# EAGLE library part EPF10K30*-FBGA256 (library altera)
EPF10K30 FLEX 10K family
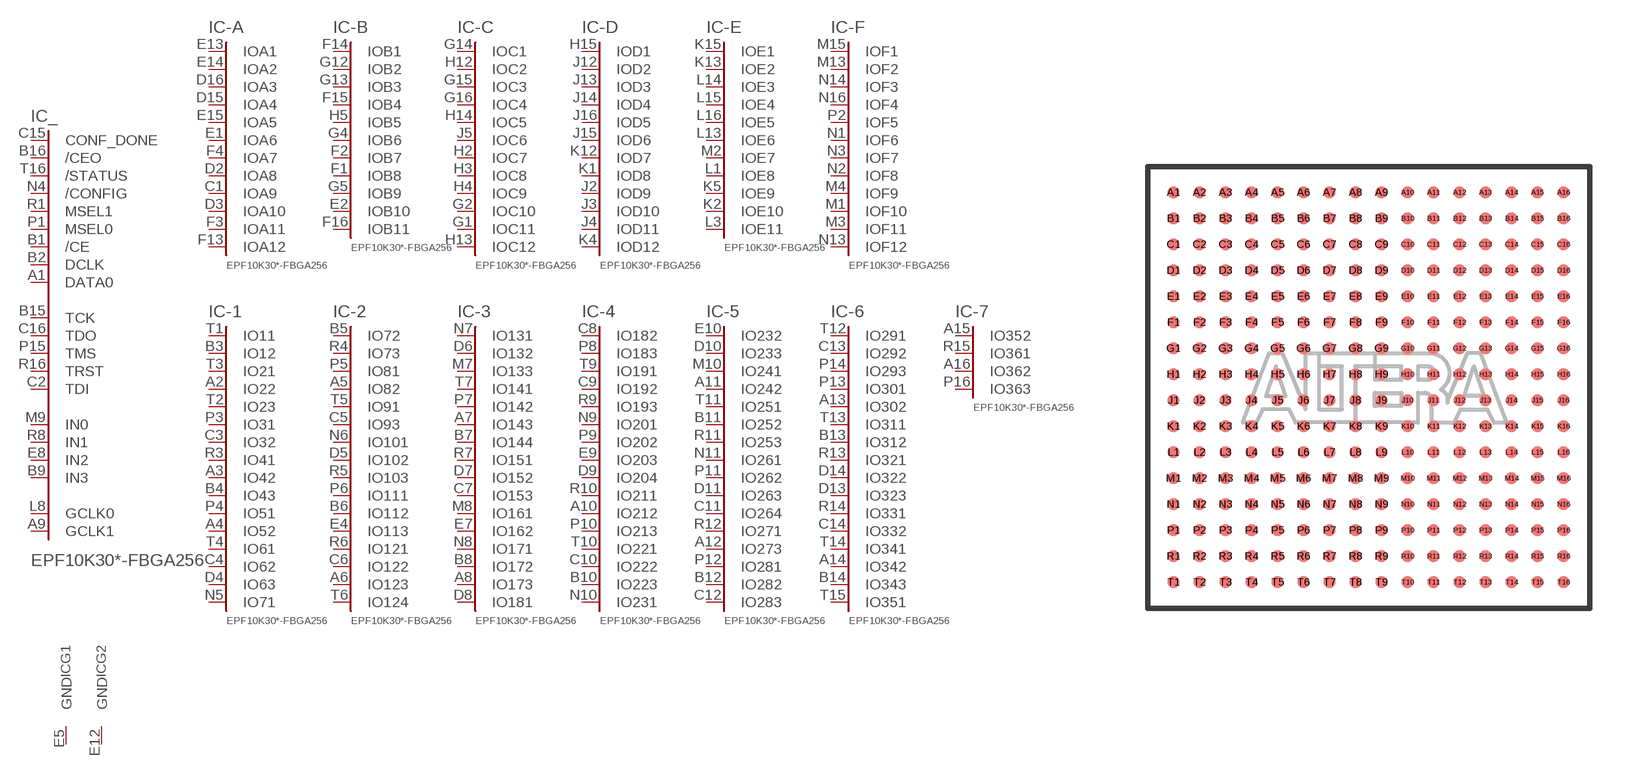
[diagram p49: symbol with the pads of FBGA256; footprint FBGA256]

Designator prefix IC; gates _=100R240C -A=A12 -B=B11 -C=C12 -D=D12 -E=E11 -F=F12 -1=71-K30EF -2=124-K30E -3=181-K30E -4=231-K30E -5=281-K30E -6=351-K30E -7=363-K30E G1=GND G2=GND G3=GND G4=GND G5=GND G6=GND G7=GND G8=GND G9=GND G10=GND G11=GND G12=GND G13=GND G14=GND G15=GND G16=GND G17=GND G18=GND NC1=NC NC2=NC NC3=NC NC4=NC NC5=NC NC6=NC NC7=NC NC8=NC NC9=NC NC10=NC NC11=NC NC12=NC NC13=NC NC14=NC NC15=NC V1=VCCINT V2=VCCINT V3=VCCINT V4=VCCINT V5=VCCINT V6=VCCINT V7=VCCINT V8=VCCINT V9=VCCINT V10=VCCINT V11=VCCINT V12=VCCINT V13=VCCINT V14=VCCINT V15=VCCINT V16=VCCINT V17=VCCINT V18=VCCINT VO1=VCCIO VO2=VCCIO VO3=VCCIO VO4=VCCIO VO5=VCCIO VO6=VCCIO VO7=VCCIO VO8=VCCIO VO9=VCCIO VO10=VCCIO VO11=VCCIO VO12=VCCIO VO13=VCCIO VO14=VCCIO VO15=VCCIO

## EPF10K30-FBGA256 (MPN: EPF10K30EFC256-3N; OC_FARNELL: 1549394; OC_NEWARK: 51R8977), EPF10K30A-FBGA256 (MPN: EPF10K30AQC240-3N; OC_FARNELL: 1549384; OC_NEWARK: 51R8956)  [FBGA256]
A1  _:DATA0  in
A2  -1:IO22
A3  -1:IO42
A4  -1:IO52
A5  -2:IO82
A6  -2:IO123
A7  -3:IO143
A8  -3:IO173
A9  _:GCLK1  in
A10  -4:IO212
A11  -5:IO242
A12  -5:IO273
A13  -6:IO302
A14  -6:IO342
A15  -7:IO352
A16  -7:IO362
B1  _:/CE  in
B2  _:DCLK  in
B3  -1:IO12
B4  -1:IO43
B5  -2:IO72
B6  -2:IO112
B7  -3:IO144
B8  -3:IO172
B9  _:IN3  in
B10  -4:IO223
B11  -5:IO252
B12  -5:IO282
B13  -6:IO312
B14  -6:IO343
B15  _:TCK
B16  _:/CEO  in
C1  -A:IOA9
C2  _:TDI
C3  -1:IO32
C4  -1:IO62
C5  -2:IO93
C6  -2:IO122
C7  -3:IO153
C8  -4:IO182
C9  -4:IO192
C10  -4:IO222
C11  -5:IO264
C12  -5:IO283
C13  -6:IO292
C14  -6:IO332
C15  _:CONF_DONE  in
C16  _:TDO
D1  NC1:NC  nc
D2  -A:IOA8
D3  -A:IOA10
D4  -1:IO63
D5  -2:IO102
D6  -3:IO132
D7  -3:IO152
D8  -3:IO181
D9  -4:IO204
D10  -5:IO233
D11  -5:IO263
D12  VO1:VCCIO  pwr
D13  -6:IO323
D14  -6:IO322
D15  -A:IOA4
D16  -A:IOA3
E1  -A:IOA6
E2  -B:IOB10
E3  NC2:NC  nc
E4  -2:IO113
E5  G1:GND  pwr
E6  VO2:VCCIO  pwr
E7  -3:IO162
E8  _:IN2  in
E9  -4:IO203
E10  -5:IO232
E11  V1:VCC  pwr
E12  G2:GND  pwr
E13  -A:IOA1
E14  -A:IOA2
E15  -A:IOA5
E16  NC3:NC  nc
F1  -B:IOB8
F2  -B:IOB7
F3  -A:IOA11
F4  -A:IOA7
F5  V2:VCC  pwr
F6  G3:GND  pwr
F7  V3:VCC  pwr
F8  VO3:VCCIO  pwr
F9  V4:VCC  pwr
F10  VO4:VCCIO  pwr
F11  G4:GND  pwr
F12  V5:VCC  pwr
F13  -A:IOA12
F14  -B:IOB1
F15  -B:IOB4
F16  -B:IOB11
G1  -C:IOC11
G2  -C:IOC10
G3  NC4:NC  nc
G4  -B:IOB6
G5  -B:IOB9
G6  VO5:VCCIO  pwr
G7  G5:GND  pwr
G8  VO6:VCCIO  pwr
G9  G6:GND  pwr
G10  G7:GND  pwr
G11  VO7:VCCIO  pwr
G12  -B:IOB2
G13  -B:IOB3
G14  -C:IOC1
G15  -C:IOC3
G16  -C:IOC4
H1  NC5:NC  nc
H2  -C:IOC7
H3  -C:IOC8
H4  -C:IOC9
H5  -B:IOB5
H6  V6:VCC  pwr
H7  V7:VCC  pwr
H8  G8:GND  pwr
H9  G9:GND  pwr
H10  V8:VCC  pwr
H11  VO8:VCCIO  pwr
H12  -C:IOC2
H13  -C:IOC12
H14  -C:IOC5
H15  -D:IOD1
H16  NC6:NC  nc
J1  NC7:NC  nc
J2  -D:IOD9
J3  -D:IOD10
J4  -D:IOD11
J5  -C:IOC6
J6  VO9:VCCIO  pwr
J7  V9:VCC  pwr
J8  G10:GND  pwr
J9  G11:GND  pwr
J10  V10:VCC  pwr
J11  V11:VCC  pwr
J12  -D:IOD2
J13  -D:IOD3
J14  -D:IOD4
J15  -D:IOD6
J16  -D:IOD5
K1  -D:IOD8
K2  -E:IOE10
K3  NC8:NC  nc
K4  -D:IOD12
K5  -E:IOE9
K6  VO10:VCCIO  pwr
K7  G12:GND  pwr
K8  VO11:VCCIO  pwr
K9  V12:VCC  pwr
K10  G13:GND  pwr
K11  VO12:VCCIO  pwr
K12  -D:IOD7
K13  -E:IOE2
K14  NC9:NC  nc
K15  -E:IOE1
K16  NC10:NC  nc
L1  -E:IOE8
L2  NC11:NC  nc
L3  -E:IOE11
L4  NC12:NC  nc
L5  V13:VCC  pwr
L6  G14:GND  pwr
L7  V14:VCC  pwr
L8  _:GCLK0  in
L9  V15:VCC  pwr
L10  VO13:VCCIO  pwr
L11  G15:GND  pwr
L12  V16:VCC  pwr
L13  -E:IOE6
L14  -E:IOE3
L15  -E:IOE4
L16  -E:IOE5
M1  -F:IOF10
M2  -E:IOE7
M3  -F:IOF11
M4  -F:IOF9
M5  G16:GND  pwr
M6  VO14:VCCIO  pwr
M7  -3:IO133
M8  -3:IO161
M9  _:IN0  in
M10  -5:IO241
M11  V17:VCC  pwr
M12  G17:GND  pwr
M13  -F:IOF2
M14  NC13:NC  nc
M15  -F:IOF1
M16  NC14:NC  nc
N1  -F:IOF6
N2  -F:IOF8
N3  -F:IOF7
N4  _:/CONFIG  in
N5  -1:IO71
N6  -2:IO101
N7  -3:IO131
N8  -3:IO171
N9  -4:IO201
N10  -4:IO231
N11  -5:IO261
N12  VO15:VCCIO  pwr
N13  -F:IOF12
N14  -F:IOF3
N15  NC15:NC  nc
N16  -F:IOF4
P1  _:MSEL0  in
P2  -F:IOF5
P3  -1:IO31
P4  -1:IO51
P5  -2:IO81
P6  -2:IO111
P7  -3:IO142
P8  -4:IO183
P9  -4:IO202
P10  -4:IO213
P11  -5:IO262
P12  -5:IO281
P13  -6:IO301
P14  -6:IO293
P15  _:TMS
P16  -7:IO363
R1  _:MSEL1  in
R2  V18:VCC  pwr
R3  -1:IO41
R4  -2:IO73
R5  -2:IO103
R6  -2:IO121
R7  -3:IO151
R8  _:IN1  in
R9  -4:IO193
R10  -4:IO211
R11  -5:IO253
R12  -5:IO271
R13  -6:IO321
R14  -6:IO331
R15  -7:IO361
R16  _:TRST
T1  -1:IO11
T2  -1:IO23
T3  -1:IO21
T4  -1:IO61
T5  -2:IO91
T6  -2:IO124
T7  -3:IO141
T8  G18:GND  pwr
T9  -4:IO191
T10  -4:IO221
T11  -5:IO251
T12  -6:IO291
T13  -6:IO311
T14  -6:IO341
T15  -6:IO351
T16  _:/STATUS  in

## Footprint FBGA256 (pad centres in mm)
Fine Ball Grid Array
smd 0.45 x 0.45: A1 -7.5,7.5; A2 -6.5,7.5; A3 -5.5,7.5; A4 -4.5,7.5; A5 -3.5,7.5; A6 -2.5,7.5; A7 -1.5,7.5; A8 -0.5,7.5; A9 0.5,7.5; A10 1.5,7.5; A11 2.5,7.5; A12 3.5,7.5; A13 4.5,7.5; A14 5.5,7.5; A15 6.5,7.5; A16 7.5,7.5; B1 -7.5,6.5; B2 -6.5,6.5; B3 -5.5,6.5; B4 -4.5,6.5; B5 -3.5,6.5; B6 -2.5,6.5; B7 -1.5,6.5; B8 -0.5,6.5; B9 0.5,6.5; B10 1.5,6.5; B11 2.5,6.5; B12 3.5,6.5; B13 4.5,6.5; B14 5.5,6.5; B15 6.5,6.5; B16 7.5,6.5; C1 -7.5,5.5; C2 -6.5,5.5; C3 -5.5,5.5; C4 -4.5,5.5; C5 -3.5,5.5; C6 -2.5,5.5; C7 -1.5,5.5; C8 -0.5,5.5; C9 0.5,5.5; C10 1.5,5.5; C11 2.5,5.5; C12 3.5,5.5; C13 4.5,5.5; C14 5.5,5.5; C15 6.5,5.5; C16 7.5,5.5; D1 -7.5,4.5; D2 -6.5,4.5; D3 -5.5,4.5; D4 -4.5,4.5; D5 -3.5,4.5; D6 -2.5,4.5; D7 -1.5,4.5; D8 -0.5,4.5; D9 0.5,4.5; D10 1.5,4.5; D11 2.5,4.5; D12 3.5,4.5; D13 4.5,4.5; D14 5.5,4.5; D15 6.5,4.5; D16 7.5,4.5; E1 -7.5,3.5; E2 -6.5,3.5; E3 -5.5,3.5; E4 -4.5,3.5; E5 -3.5,3.5; E6 -2.5,3.5; E7 -1.5,3.5; E8 -0.5,3.5; E9 0.5,3.5; E10 1.5,3.5; E11 2.5,3.5; E12 3.5,3.5; E13 4.5,3.5; E14 5.5,3.5; E15 6.5,3.5; E16 7.5,3.5; F1 -7.5,2.5; F2 -6.5,2.5; F3 -5.5,2.5; F4 -4.5,2.5; F5 -3.5,2.5; F6 -2.5,2.5; F7 -1.5,2.5; F8 -0.5,2.5; F9 0.5,2.5; F10 1.5,2.5; F11 2.5,2.5; F12 3.5,2.5; F13 4.5,2.5; F14 5.5,2.5; F15 6.5,2.5; F16 7.5,2.5; G1 -7.5,1.5; G2 -6.5,1.5; G3 -5.5,1.5; G4 -4.5,1.5; G5 -3.5,1.5; G6 -2.5,1.5; G7 -1.5,1.5; G8 -0.5,1.5; G9 0.5,1.5; G10 1.5,1.5; G11 2.5,1.5; G12 3.5,1.5; G13 4.5,1.5; G14 5.5,1.5; G15 6.5,1.5; G16 7.5,1.5; H1 -7.5,0.5; H2 -6.5,0.5; H3 -5.5,0.5; H4 -4.5,0.5; H5 -3.5,0.5; H6 -2.5,0.5; H7 -1.5,0.5; H8 -0.5,0.5; H9 0.5,0.5; H10 1.5,0.5; H11 2.5,0.5; H12 3.5,0.5; H13 4.5,0.5; H14 5.5,0.5; H15 6.5,0.5; H16 7.5,0.5; J1 -7.5,-0.5; J2 -6.5,-0.5; J3 -5.5,-0.5; J4 -4.5,-0.5; J5 -3.5,-0.5; J6 -2.5,-0.5; J7 -1.5,-0.5; J8 -0.5,-0.5; J9 0.5,-0.5; J10 1.5,-0.5; J11 2.5,-0.5; J12 3.5,-0.5; J13 4.5,-0.5; J14 5.5,-0.5; J15 6.5,-0.5; J16 7.5,-0.5; K1 -7.5,-1.5; K2 -6.5,-1.5; K3 -5.5,-1.5; K4 -4.5,-1.5; K5 -3.5,-1.5; K6 -2.5,-1.5; K7 -1.5,-1.5; K8 -0.5,-1.5; K9 0.5,-1.5; K10 1.5,-1.5; K11 2.5,-1.5; K12 3.5,-1.5; K13 4.5,-1.5; K14 5.5,-1.5; K15 6.5,-1.5; K16 7.5,-1.5; L1 -7.5,-2.5; L2 -6.5,-2.5; L3 -5.5,-2.5; L4 -4.5,-2.5; L5 -3.5,-2.5; L6 -2.5,-2.5; L7 -1.5,-2.5; L8 -0.5,-2.5; L9 0.5,-2.5; L10 1.5,-2.5; L11 2.5,-2.5; L12 3.5,-2.5; L13 4.5,-2.5; L14 5.5,-2.5; L15 6.5,-2.5; L16 7.5,-2.5; M1 -7.5,-3.5; M2 -6.5,-3.5; M3 -5.5,-3.5; M4 -4.5,-3.5; M5 -3.5,-3.5; M6 -2.5,-3.5; M7 -1.5,-3.5; M8 -0.5,-3.5; M9 0.5,-3.5; M10 1.5,-3.5; M11 2.5,-3.5; M12 3.5,-3.5; M13 4.5,-3.5; M14 5.5,-3.5; M15 6.5,-3.5; M16 7.5,-3.5; N1 -7.5,-4.5; N2 -6.5,-4.5; N3 -5.5,-4.5; N4 -4.5,-4.5; N5 -3.5,-4.5; N6 -2.5,-4.5; N7 -1.5,-4.5; N8 -0.5,-4.5; N9 0.5,-4.5; N10 1.5,-4.5; N11 2.5,-4.5; N12 3.5,-4.5; N13 4.5,-4.5; N14 5.5,-4.5; N15 6.5,-4.5; N16 7.5,-4.5; P1 -7.5,-5.5; P2 -6.5,-5.5; P3 -5.5,-5.5; P4 -4.5,-5.5; P5 -3.5,-5.5; P6 -2.5,-5.5; P7 -1.5,-5.5; P8 -0.5,-5.5; P9 0.5,-5.5; P10 1.5,-5.5; P11 2.5,-5.5; P12 3.5,-5.5; P13 4.5,-5.5; P14 5.5,-5.5; P15 6.5,-5.5; P16 7.5,-5.5; R1 -7.5,-6.5; R2 -6.5,-6.5; R3 -5.5,-6.5; R4 -4.5,-6.5; R5 -3.5,-6.5; R6 -2.5,-6.5; R7 -1.5,-6.5; R8 -0.5,-6.5; R9 0.5,-6.5; R10 1.5,-6.5; R11 2.5,-6.5; R12 3.5,-6.5; R13 4.5,-6.5; R14 5.5,-6.5; R15 6.5,-6.5; R16 7.5,-6.5; T1 -7.5,-7.5; T2 -6.5,-7.5; T3 -5.5,-7.5; T4 -4.5,-7.5; T5 -3.5,-7.5; T6 -2.5,-7.5; T7 -1.5,-7.5; T8 -0.5,-7.5; T9 0.5,-7.5; T10 1.5,-7.5; T11 2.5,-7.5; T12 3.5,-7.5; T13 4.5,-7.5; T14 5.5,-7.5; T15 6.5,-7.5; T16 7.5,-7.5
